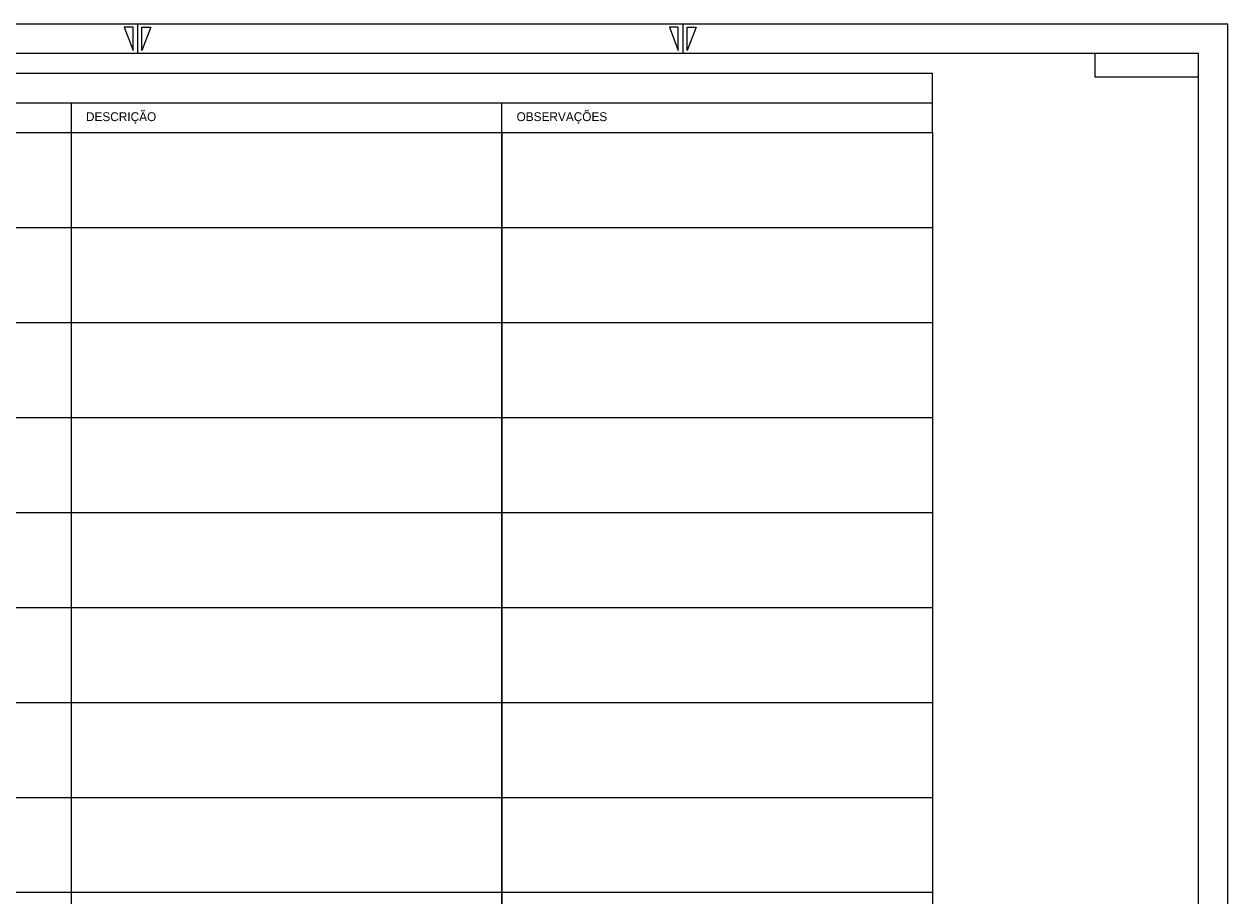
# Model space of a CAD drawing. Extents: x 563 to 3226, y 358 to 960.
# Drawn here: x 2817.7 to 3226.2, y 656.2 to 952 of the extents above; entities that cross this region are included whole.
import ezdxf

# ---------------------------------------------------------------- set-up
doc = ezdxf.new("R2010")
doc.units = 0
doc.layers.add('Default', color=7, linetype='Continuous')
doc.layers.add('New Level (0)', color=7, linetype='Continuous')

msp = doc.modelspace()

# ---------------------------------------------------------------- linework, layer by layer
at = {"layer": 'New Level (0)'}
for p, q in [((3226.19, 951.96), (2385.19, 951.96)), ((3226.19, 951.96), (2385.19, 951.96)), ((2856.19, 951.96), (2856.19, 941.96)), ((3041.19, 951.96), (3041.19, 941.96)), ((3226.19, 357.96), (3226.19, 951.96)), ((3226.19, 357.96), (3226.19, 951.96)), ((2854.69, 950.96), (2851.69, 950.96)), ((2851.69, 950.96), (2854.69, 942.96)), ((2854.69, 942.96), (2854.69, 950.96)), ((2857.69, 942.96), (2857.69, 950.96)), ((2857.69, 950.96), (2860.69, 950.96)), ((2860.69, 950.96), (2857.69, 942.96)), ((3039.69, 950.96), (3036.69, 950.96)), ((3036.69, 950.96), (3039.69, 942.96)), ((3039.69, 942.96), (3039.69, 950.96)), ((3042.69, 942.96), (3042.69, 950.96)), ((3042.69, 950.96), (3045.69, 950.96)), ((3045.69, 950.96), (3042.69, 942.96)), ((3216.19, 941.96), (2395.19, 941.96)), ((3181.19, 933.96), (3181.19, 941.96)), ((3216.19, 367.96), (3216.19, 941.96)), ((3216.19, 367.96), (3216.19, 941.96)), ((2425.75, 935.35), (3125.92, 935.35)), ((3125.92, 915.21), (3125.92, 935.35)), ((3216.19, 933.96), (3181.19, 933.96)), ((2775.83, 925.28), (3125.92, 925.28)), ((2833.67, 925.28), (2833.67, 429.83)), ((2979.79, 915.21), (2979.79, 925.28)), ((2425.75, 882.98), (3125.92, 882.98)), ((2425.75, 850.75), (3125.92, 850.75)), ((2425.75, 818.53), (3125.92, 818.53)), ((2425.75, 786.3), (3125.92, 786.3)), ((2425.75, 754.07), (3125.92, 754.07)), ((2425.75, 721.84), (3125.92, 721.84)), ((2425.75, 689.61), (3125.92, 689.61)), ((2425.75, 657.39), (3125.92, 657.39))]:
    msp.add_line(p, q, dxfattribs=at)
for points in [[(2775.83, 915.21), (2979.79, 915.21), (2979.79, 429.83), (2775.83, 429.83)], [(2979.79, 915.21), (3125.92, 915.21), (3125.92, 429.83), (2979.79, 429.83)]]:
    msp.add_lwpolyline(points, close=True, dxfattribs=at)

# ---------------------------------------------------------------- texts
at = {"layer": 'Default'}
for s, p in [('DESCRIÇÃO', (2838.68, 919.04)), ('OBSERVAÇÕES', (2984.8, 919.04))]:
    msp.add_text(s, height=3, dxfattribs=at).set_placement(p)

doc.saveas('drawing.dxf')
